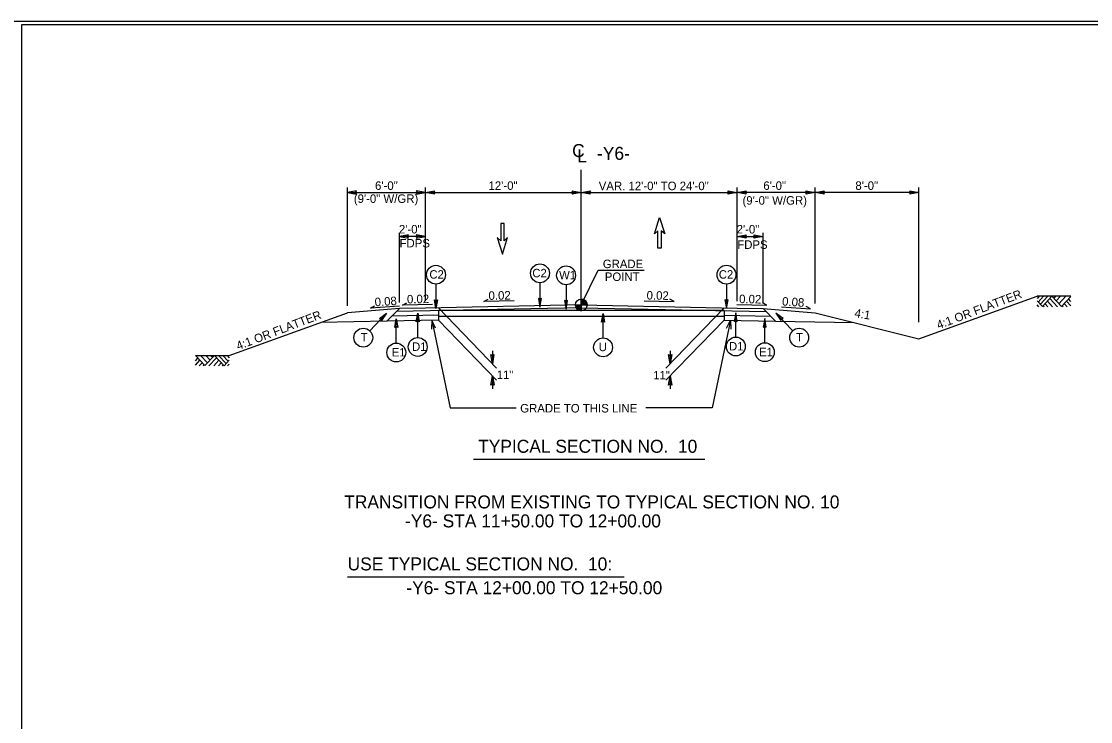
# Model space of a CAD drawing. Extents: x 1901670 to 1902225, y 193498 to 194278.
# Drawn here: x 1901982.5 to 1902064.8, y 193661.9 to 193715.8 of the extents above; entities that cross this region are included whole.
import ezdxf

# ---------------------------------------------------------------- set-up
doc = ezdxf.new("R2010")
doc.units = 0
for name, color, linetype in [('Old_Level_1', 7, 'Continuous'), ('Old_Level_11', 7, 'Continuous'), ('Old_Level_2', 7, 'Continuous'), ('Old_Level_20', 7, 'Continuous'), ('Prop Dimension', 7, 'Continuous'), ('Prop Dimension Text', 7, 'Continuous'), ('Sheet Border Standard 30in CELL', 7, 'Continuous'), ('Sheet Plot Border Inside CELL', 7, 'Continuous'), ('Typical Hinge Slope Interstate CELL', 7, 'Continuous'), ('Typical Pavement Slope CELL', 7, 'Continuous'), ('Typical Terminator CELL', 7, 'Continuous'), ('Typical Text Grade Point CELL', 7, 'Continuous')]:
    doc.layers.add(name, color=color, linetype=linetype)

# ---------------------------------------------------------------- blocks, each defined once
blk = doc.blocks.new('TERMINATOR')
at = {"layer": 'Typical Terminator CELL'}
blk.add_lwpolyline([(-0.469, 0.081), (0, 0), (-0.471, -0.083), (-0.411, 0)], close=True, dxfattribs=at)

msp = doc.modelspace()

# ---------------------------------------------------------------- linework, layer by layer
at = {"layer": 'Old_Level_1'}
for p, q in [((1902025.621, 193693.956), (1902025.621, 193704.336)), ((1902043.616, 193694.065), (1902043.616, 193702.976)), ((1902018.135, 193694.218), (1902018.468, 193694.385)), ((1902020.45, 193694.267), (1902018.135, 193694.218)), ((1902025.621, 193693.956), (1902025.621, 193694.406)), ((1902030.469, 193694.267), (1902032.784, 193694.218)), ((1902032.784, 193694.218), (1902032.451, 193694.385)), ((1902060.879, 193694.619), (1902060.709, 193694.436)), ((1902061.113, 193693.822), (1902060.709, 193694.257)), ((1902061.199, 193694.619), (1902060.785, 193694.175)), ((1902061.532, 193694.619), (1902060.952, 193693.996)), ((1902061.854, 193694.618), (1902061.113, 193693.822)), ((1902061.905, 193693.814), (1902061.505, 193694.243)), ((1902062.275, 193693.814), (1902061.689, 193694.442)), ((1902062.586, 193693.832), (1902061.854, 193694.618)), ((1902062.118, 193694.619), (1902061.985, 193694.476)), ((1902062.52, 193694.619), (1902062.187, 193694.26)), ((1902062.918, 193694.619), (1902062.385, 193694.046)), ((1902063.309, 193694.611), (1902062.586, 193693.832)), ((1902063.309, 193693.877), (1902062.967, 193694.243)), ((1902063.309, 193694.209), (1902063.124, 193694.41)), ((1902011.621, 193693.676), (1902007.621, 193693.343)), ((1902009.391, 193693.706), (1902009.716, 193693.888)), ((1902011.626, 193693.852), (1902009.391, 193693.706)), ((1902010.654, 193692.709), (1902011.621, 193693.676)), ((1902025.621, 193693.737), (1902011.398, 193693.453)), ((1902013.621, 193693.716), (1902011.621, 193693.676)), ((1902011.859, 193693.943), (1902012.192, 193694.11)), ((1902014.174, 193693.992), (1902011.859, 193693.943)), ((1902025.621, 193693.956), (1902013.621, 193693.716)), ((1902014.623, 193693.736), (1902019.098, 193689.099)), ((1902036.614, 193693.517), (1902014.623, 193693.517)), ((1902014.623, 193693.517), (1902014.623, 193692.788)), ((1902025.171, 193693.956), (1902025.621, 193693.956)), ((1902025.62, 193693.506), (1902025.621, 193693.956)), ((1902025.621, 193693.956), (1902025.62, 193693.506)), ((1902026.071, 193693.956), (1902025.621, 193693.956)), ((1902025.621, 193693.956), (1902037.616, 193693.716)), ((1902025.621, 193693.737), (1902039.84, 193693.453)), ((1902036.614, 193693.736), (1902032.14, 193689.099)), ((1902036.614, 193693.517), (1902036.614, 193692.789)), ((1902037.587, 193693.986), (1902039.903, 193693.938)), ((1902037.616, 193693.716), (1902039.616, 193693.676)), ((1902039.903, 193693.938), (1902039.57, 193694.105)), ((1902040.583, 193692.709), (1902039.616, 193693.676)), ((1902039.616, 193693.676), (1902043.616, 193693.343)), ((1902041.028, 193693.803), (1902043.263, 193693.658)), ((1902043.263, 193693.658), (1902042.938, 193693.839)), ((1902060.843, 193693.814), (1902060.709, 193693.957)), ((1902061.244, 193693.814), (1902061.175, 193693.888)), ((1902061.539, 193693.814), (1902061.322, 193694.047)), ((1902062.711, 193693.814), (1902062.639, 193693.89)), ((1902063.021, 193693.814), (1902062.794, 193694.057)), ((1902010.654, 193692.709), (1902005.581, 193692.608)), ((1902014.623, 193692.788), (1902010.654, 193692.709)), ((1902014.623, 193693.153), (1902011.026, 193693.081)), ((1902036.614, 193693.07), (1902014.623, 193693.07)), ((1902014.623, 193692.788), (1902019.1, 193688.164)), ((1902036.614, 193692.789), (1902032.138, 193688.164)), ((1902036.614, 193693.153), (1902040.211, 193693.081)), ((1902036.614, 193692.789), (1902040.583, 193692.709)), ((1902040.583, 193692.709), (1902046.635, 193692.588)), ((1902043.616, 193693.343), (1902051.616, 193691.343)), ((1902018.779, 193690.428), (1902018.779, 193689.428)), ((1902032.459, 193690.428), (1902032.459, 193689.428)), ((1901995.928, 193690.059), (1901996.652, 193689.28)), ((1901995.928, 193689.658), (1901996.114, 193689.858)), ((1901995.928, 193689.325), (1901996.27, 193689.691)), ((1901996.216, 193689.262), (1901996.443, 193689.505)), ((1901996.319, 193690.067), (1901996.852, 193689.494)), ((1901996.527, 193689.262), (1901996.598, 193689.338)), ((1901996.652, 193689.28), (1901997.383, 193690.066)), ((1901996.717, 193690.067), (1901997.05, 193689.708)), ((1901996.962, 193689.262), (1901997.548, 193689.89)), ((1901997.119, 193690.067), (1901997.252, 193689.924)), ((1901997.332, 193689.262), (1901997.732, 193689.691)), ((1901997.383, 193690.066), (1901998.124, 193689.27)), ((1901997.698, 193689.262), (1901997.915, 193689.495)), ((1901997.705, 193690.067), (1901998.285, 193689.444)), ((1901997.993, 193689.262), (1901998.062, 193689.336)), ((1901998.038, 193690.067), (1901998.452, 193689.623)), ((1901998.124, 193689.27), (1901998.528, 193689.705)), ((1901998.358, 193690.067), (1901998.528, 193689.884)), ((1901998.394, 193689.262), (1901998.528, 193689.405)), ((1902018.781, 193688.493), (1902018.781, 193687.493)), ((1902032.457, 193688.493), (1902032.457, 193687.493))]:
    msp.add_line(p, q, dxfattribs=at)
for points in [[(1902025.625, 193694.406), (1902025.625, 193694.406), (1902025.625, 193693.956)], [(1902025.634, 193694.406), (1902025.634, 193693.956)], [(1902025.643, 193694.405), (1902025.643, 193693.956)], [(1902025.652, 193694.405), (1902025.652, 193693.956)], [(1902025.661, 193694.404), (1902025.661, 193693.956)], [(1902025.67, 193694.403), (1902025.67, 193693.956)], [(1902025.679, 193694.402), (1902025.679, 193693.956)], [(1902025.688, 193694.401), (1902025.688, 193693.956)], [(1902025.697, 193694.4), (1902025.697, 193693.956)], [(1902025.706, 193694.398), (1902025.706, 193693.956)], [(1902025.715, 193694.396), (1902025.715, 193693.956)], [(1902025.724, 193694.394), (1902025.724, 193693.956)], [(1902025.733, 193694.392), (1902025.733, 193693.956)], [(1902025.742, 193694.389), (1902025.742, 193693.956)], [(1902025.751, 193694.387), (1902025.751, 193693.956)], [(1902025.76, 193694.384), (1902025.76, 193693.956)], [(1902025.769, 193694.381), (1902025.769, 193693.956)], [(1902025.778, 193694.378), (1902025.778, 193693.956)], [(1902025.787, 193694.374), (1902025.787, 193693.956)], [(1902025.796, 193694.37), (1902025.796, 193693.956)], [(1902025.805, 193694.366), (1902025.805, 193693.956)], [(1902025.814, 193694.362), (1902025.814, 193693.956)], [(1902025.823, 193694.358), (1902025.823, 193693.956)], [(1902025.832, 193694.353), (1902025.832, 193693.956)], [(1902025.841, 193694.348), (1902025.841, 193693.956)], [(1902025.85, 193694.343), (1902025.85, 193693.956)], [(1902025.859, 193694.338), (1902025.859, 193693.956)], [(1902025.868, 193694.332), (1902025.868, 193693.956)], [(1902025.877, 193694.326), (1902025.877, 193693.956)], [(1902025.886, 193694.319), (1902025.886, 193693.956)], [(1902025.895, 193694.313), (1902025.895, 193693.956)], [(1902025.904, 193694.306), (1902025.904, 193693.956)], [(1902025.913, 193694.298), (1902025.913, 193693.956)], [(1902025.922, 193694.29), (1902025.922, 193693.956)], [(1902025.931, 193694.282), (1902025.931, 193693.956)], [(1902025.94, 193694.273), (1902025.94, 193693.956)], [(1902025.949, 193694.264), (1902025.949, 193693.956)], [(1902025.958, 193694.254), (1902025.958, 193693.956)], [(1902025.967, 193694.243), (1902025.967, 193693.956)], [(1902025.976, 193694.232), (1902025.976, 193693.956)], [(1902063.309, 193694.619), (1902060.709, 193694.619)], [(1902025.173, 193693.956), (1902025.173, 193693.907)], [(1902025.182, 193693.956), (1902025.182, 193693.854)], [(1902025.191, 193693.956), (1902025.191, 193693.822)], [(1902025.2, 193693.956), (1902025.2, 193693.795)], [(1902025.209, 193693.956), (1902025.209, 193693.774)], [(1902025.218, 193693.956), (1902025.218, 193693.755)], [(1902025.227, 193693.956), (1902025.227, 193693.738)], [(1902025.236, 193693.956), (1902025.236, 193693.722)], [(1902025.245, 193693.956), (1902025.245, 193693.708)], [(1902025.254, 193693.956), (1902025.254, 193693.695)], [(1902025.263, 193693.956), (1902025.263, 193693.683)], [(1902025.272, 193693.956), (1902025.272, 193693.672)], [(1902025.281, 193693.956), (1902025.281, 193693.661)], [(1902025.29, 193693.956), (1902025.29, 193693.651)], [(1902025.299, 193693.956), (1902025.299, 193693.641)], [(1902025.308, 193693.956), (1902025.308, 193693.632)], [(1902025.317, 193693.956), (1902025.317, 193693.624)], [(1902025.326, 193693.956), (1902025.326, 193693.616)], [(1902025.335, 193693.956), (1902025.335, 193693.608)], [(1902025.344, 193693.956), (1902025.344, 193693.601)], [(1902025.353, 193693.956), (1902025.353, 193693.594)], [(1902025.362, 193693.956), (1902025.362, 193693.588)], [(1902025.371, 193693.956), (1902025.371, 193693.582)], [(1902025.38, 193693.956), (1902025.38, 193693.576)], [(1902025.389, 193693.956), (1902025.389, 193693.57)], [(1902025.398, 193693.956), (1902025.398, 193693.565)], [(1902025.407, 193693.956), (1902025.407, 193693.56)], [(1902025.416, 193693.956), (1902025.416, 193693.555)], [(1902025.425, 193693.956), (1902025.425, 193693.551)], [(1902025.434, 193693.956), (1902025.434, 193693.547)], [(1902025.443, 193693.956), (1902025.443, 193693.543)], [(1902025.452, 193693.956), (1902025.452, 193693.539)], [(1902025.461, 193693.956), (1902025.461, 193693.535)], [(1902025.47, 193693.956), (1902025.47, 193693.532)], [(1902025.479, 193693.956), (1902025.479, 193693.529)], [(1902025.488, 193693.956), (1902025.488, 193693.526)], [(1902025.497, 193693.956), (1902025.497, 193693.524)], [(1902025.506, 193693.956), (1902025.506, 193693.521)], [(1902025.515, 193693.956), (1902025.515, 193693.519)], [(1902025.524, 193693.956), (1902025.524, 193693.517)], [(1902025.533, 193693.956), (1902025.533, 193693.515)], [(1902025.542, 193693.956), (1902025.542, 193693.513)], [(1902025.551, 193693.956), (1902025.551, 193693.512)], [(1902025.56, 193693.956), (1902025.56, 193693.51)], [(1902025.569, 193693.956), (1902025.569, 193693.509)], [(1902025.578, 193693.956), (1902025.578, 193693.508)], [(1902025.587, 193693.956), (1902025.587, 193693.507)], [(1902025.596, 193693.956), (1902025.596, 193693.507)], [(1902025.605, 193693.956), (1902025.605, 193693.506)], [(1902025.614, 193693.956), (1902025.614, 193693.506), (1902025.614, 193693.506)], [(1902025.985, 193694.22), (1902025.985, 193693.956)], [(1902025.994, 193694.207), (1902025.994, 193693.956)], [(1902026.003, 193694.193), (1902026.003, 193693.956)], [(1902026.012, 193694.178), (1902026.012, 193693.956)], [(1902026.021, 193694.162), (1902026.021, 193693.956)], [(1902026.03, 193694.143), (1902026.03, 193693.956)], [(1902026.039, 193694.122), (1902026.039, 193693.956)], [(1902026.048, 193694.097), (1902026.048, 193693.956)], [(1902026.057, 193694.066), (1902026.057, 193693.956)], [(1902026.066, 193694.02), (1902026.066, 193693.956)], [(1902014.405, 193692.161), (1902014.112, 193692.77), (1902014.084, 193692.095)], [(1902014.112, 193692.77), (1902015.519, 193686.042), (1902020.607, 193686.042)], [(1902037.096, 193692.77), (1902035.689, 193686.042), (1902030.602, 193686.042)], [(1902036.803, 193692.161), (1902037.096, 193692.77), (1902037.124, 193692.095)], [(1901995.928, 193690.067), (1901998.528, 193690.067)]]:
    msp.add_lwpolyline(points, dxfattribs=at)
msp.add_circle((1902025.621, 193693.956), 0.45, dxfattribs=at)
for start, end in [(359.99048, 89.99048), (179.99048, 269.99048)]:
    msp.add_arc((1902025.621, 193693.956), 0.45, start, end, dxfattribs=at)
at = {"layer": 'Old_Level_11'}
for p, q in [((1902014.44, 193695.555), (1902014.44, 193693.681)), ((1902022.445, 193695.659), (1902022.445, 193693.785)), ((1902024.453, 193695.505), (1902024.453, 193693.631)), ((1902036.798, 193695.555), (1902036.798, 193693.681)), ((1902009.346, 193691.96), (1902010.636, 193693.319)), ((1902011.384, 193691.015), (1902011.384, 193692.889)), ((1902013.033, 193691.447), (1902013.033, 193693.322)), ((1902027.299, 193691.415), (1902027.299, 193693.29)), ((1902037.515, 193691.479), (1902037.515, 193693.353)), ((1902039.747, 193691.039), (1902039.747, 193692.913)), ((1902041.897, 193691.96), (1902040.606, 193693.319)), ((1902017.328, 193682.081), (1902035.127, 193682.081)), ((1902007.638, 193673.031), (1902028.934, 193673.031))]:
    msp.add_line(p, q, dxfattribs=at)
for points in [[(1902014.555, 193694.353), (1902014.44, 193693.681), (1902014.32, 193694.356), (1902014.44, 193694.27)], [(1902022.329, 193694.456), (1902022.445, 193693.785), (1902022.564, 193694.46), (1902022.445, 193694.374)], [(1902024.338, 193694.302), (1902024.453, 193693.631), (1902024.573, 193694.306), (1902024.453, 193694.22)], [(1902036.682, 193694.353), (1902036.798, 193693.681), (1902036.917, 193694.356), (1902036.798, 193694.271)], [(1902010.09, 193692.911), (1902010.636, 193693.319), (1902010.258, 193692.747), (1902010.23, 193692.891)], [(1902011.268, 193692.218), (1902011.384, 193692.889), (1902011.503, 193692.214), (1902011.384, 193692.3)], [(1902012.917, 193692.65), (1902013.033, 193693.322), (1902013.152, 193692.646), (1902013.033, 193692.732)], [(1902027.183, 193692.618), (1902027.299, 193693.29), (1902027.418, 193692.614), (1902027.299, 193692.7)], [(1902037.63, 193692.682), (1902037.515, 193693.353), (1902037.395, 193692.678), (1902037.515, 193692.764)], [(1902039.862, 193692.242), (1902039.747, 193692.913), (1902039.627, 193692.238), (1902039.747, 193692.324)], [(1902041.152, 193692.911), (1902040.606, 193693.319), (1902040.984, 193692.747), (1902041.012, 193692.891)]]:
    msp.add_lwpolyline(points, close=True, dxfattribs=at)
for centre in [(1902014.44, 193696.28), (1902022.445, 193696.384), (1902024.453, 193696.23), (1902036.798, 193696.281), (1902008.846, 193691.434), (1902042.396, 193691.434), (1902011.384, 193690.29), (1902013.033, 193690.722), (1902027.299, 193690.69), (1902037.515, 193690.754), (1902039.747, 193690.314)]:
    msp.add_circle(centre, 0.725, dxfattribs=at)
at = {"layer": 'Prop Dimension'}
for p, q in [((1902013.621, 193695.285), (1902013.621, 193702.976)), ((1902013.621, 193702.606), (1902025.621, 193702.606)), ((1902025.616, 193702.606), (1902037.616, 193702.606)), ((1902037.616, 193695.285), (1902037.616, 193702.976))]:
    msp.add_line(p, q, dxfattribs=at)
for points in [[(1902019.945, 193699.136), (1902019.675, 193698.886), (1902019.675, 193700.22), (1902019.425, 193700.22), (1902019.425, 193698.886), (1902019.154, 193699.136), (1902019.55, 193697.865)], [(1902019.945, 193699.136), (1902019.675, 193698.886), (1902019.675, 193700.22), (1902019.425, 193700.22), (1902019.425, 193698.886), (1902019.154, 193699.136), (1902019.55, 193697.865)], [(1902032.042, 193699.414), (1902031.771, 193699.664), (1902031.771, 193698.331), (1902031.521, 193698.331), (1902031.521, 193699.664), (1902031.25, 193699.414), (1902031.646, 193700.685)], [(1902032.042, 193699.414), (1902031.771, 193699.664), (1902031.771, 193698.331), (1902031.521, 193698.331), (1902031.521, 193699.664), (1902031.25, 193699.414), (1902031.646, 193700.685)]]:
    msp.add_lwpolyline(points, close=True, dxfattribs=at)
at = {"layer": 'Prop Dimension Text'}
for p, q in [((1902007.621, 193694.122), (1902007.621, 193702.976)), ((1902007.621, 193693.879), (1902007.621, 193702.976)), ((1902007.621, 193702.606), (1902013.621, 193702.606)), ((1902013.621, 193694.232), (1902013.621, 193702.976)), ((1902037.616, 193694.232), (1902037.616, 193702.976)), ((1902043.616, 193702.606), (1902037.616, 193702.606)), ((1902051.616, 193702.606), (1902043.616, 193702.606)), ((1902051.616, 193692.628), (1902051.616, 193702.976)), ((1902011.621, 193694.142), (1902011.621, 193699.503)), ((1902013.621, 193699.22), (1902011.621, 193699.22)), ((1902037.616, 193699.221), (1902039.616, 193699.221)), ((1902039.616, 193694.143), (1902039.616, 193699.503))]:
    msp.add_line(p, q, dxfattribs=at)
at = {"layer": 'Sheet Border Standard 30in CELL'}
msp.add_line((1901982.644, 193715.514), (1901982.644, 193715.514), dxfattribs=at)
msp.add_lwpolyline([(1902132.544, 193715.514), (1901982.544, 193715.514), (1901982.544, 193610.514), (1902132.544, 193610.514)], close=True, dxfattribs=at)
at = {"layer": 'Sheet Plot Border Inside CELL'}
msp.add_lwpolyline([(1902133.794, 193715.769), (1901967.144, 193715.769), (1901967.144, 193610.259), (1902133.794, 193610.259)], close=True, dxfattribs=at)
at = {"layer": 'Typical Pavement Slope CELL'}
for p, q in [((1902051.616, 193691.343), (1902060.709, 193694.619)), ((1901998.528, 193690.067), (1902007.621, 193693.343))]:
    msp.add_line(p, q, dxfattribs=at)
at = {"layer": 'Typical Text Grade Point CELL'}
for p, q in [((1902025.621, 193693.956), (1902026.917, 193696.629)), ((1902026.917, 193696.629), (1902030.455, 193696.629))]:
    msp.add_line(p, q, dxfattribs=at)

# ---------------------------------------------------------------- block references
at = {"layer": 'Old_Level_1', "xscale": 1.5, "yscale": 1.5}
for p, rotation in [((1902018.779, 193689.428), -90), ((1902032.459, 193689.428), -90), ((1902018.781, 193688.493), 90), ((1902032.457, 193688.493), 90)]:
    msp.add_blockref('TERMINATOR', p, dxfattribs=dict(at, rotation=rotation))
at = {"layer": 'Prop Dimension', "xscale": 1.5, "rotation": 180}
for p, yscale in [((1902007.621, 193702.606), -1.5), ((1902013.621, 193702.606), 1.5), ((1902025.616, 193702.606), 1.5), ((1902037.616, 193702.606), 1.5), ((1902043.616, 193702.606), 1.5), ((1902011.621, 193699.22), -1.5), ((1902037.616, 193699.221), 1.5)]:
    msp.add_blockref('TERMINATOR', p, dxfattribs=dict(at, yscale=yscale))
at = {"layer": 'Prop Dimension', "xscale": 1.5}
for p, yscale in [((1902013.621, 193702.606), -1.5), ((1902025.621, 193702.606), 1.5), ((1902037.616, 193702.606), 1.5), ((1902043.616, 193702.606), 1.5), ((1902051.616, 193702.606), 1.5), ((1902013.621, 193699.22), -1.5), ((1902039.616, 193699.221), 1.5)]:
    msp.add_blockref('TERMINATOR', p, dxfattribs=dict(at, yscale=yscale))

# ---------------------------------------------------------------- texts
at = {"layer": 'Old_Level_1'}
for p in [(1902053.126, 193692.074), (1901999.215, 193690.47)]:
    msp.add_text('4:1 OR FLATTER', height=0.656, rotation=20.83423, dxfattribs=at).set_placement(p)
for s, height, p in [('11"', 0.6491, (1902019.118, 193688.253)), ('11"', 0.6491, (1902031.168, 193688.228)), ('GRADE TO THIS LINE', 0.656, (1902020.919, 193685.676))]:
    msp.add_text(s, height=height, dxfattribs=at).set_placement(p)
at = {"layer": 'Old_Level_11'}
for s, p in [('TYPICAL SECTION NO.  10', (1902017.684, 193682.575)), ('TRANSITION FROM EXISTING TO TYPICAL SECTION NO. 10', (1902007.378, 193678.296)), ('-Y6- STA 11+50.00 TO 12+00.00', (1902012.054, 193676.835)), ('USE TYPICAL SECTION NO.  10:', (1902007.638, 193673.525)), (' -Y6- STA 12+00.00 TO 12+50.00', (1902011.784, 193671.693))]:
    msp.add_text(s, height=1, dxfattribs=at).set_placement(p)
at = {"layer": 'Old_Level_2'}
msp.add_text('C', height=1, dxfattribs=at).set_placement((1902024.919, 193705.33))
for s, height, rotation, p in [('L', 1, 359.9469, (1902025.321, 193704.926)), ('-Y6-', 1, 359.9469, (1902026.836, 193705.117)), ('0.08', 0.656, 3.71657, (1902009.74, 193693.841)), ('0.02', 0.656, 1.19158, (1902012.214, 193694.062)), ('0.02', 0.656, 1.19158, (1902018.49, 193694.337)), ('0.02', 0.656, 358.80842, (1902030.646, 193694.374)), ('0.02', 0.656, 358.80842, (1902037.764, 193694.094)), ('0.08', 0.656, 356.28343, (1902041.064, 193693.912))]:
    msp.add_text(s, height=height, rotation=rotation, dxfattribs=at).set_placement(p)
at = {"layer": 'Old_Level_20'}
for s, height, p in [('C2', 0.6491, (1902021.856, 193696.078)), ('C2', 0.6491, (1902013.934, 193695.974)), ('W1', 0.6491, (1902023.916, 193695.924)), ('C2', 0.6491, (1902036.209, 193695.974)), ('T', 0.649, (1902008.644, 193691.142)), ('T', 0.649, (1902042.159, 193691.142)), ('D1', 0.6491, (1902012.6, 193690.419)), ('U', 0.649, (1902026.971, 193690.397)), ('D1', 0.6491, (1902036.993, 193690.45)), ('E1', 0.6491, (1902011.039, 193689.986)), ('E1', 0.6491, (1902039.313, 193690.01))]:
    msp.add_text(s, height=height, dxfattribs=at).set_placement(p)
at = {"layer": 'Prop Dimension'}
for s, p in [('12\'-0" ', (1902018.484, 193702.804)), ('VAR. 12\'-0" TO 24\'-0" ', (1902026.965, 193702.783)), ('8\'-0" ', (1902046.72, 193702.804))]:
    msp.add_text(s, height=0.656, dxfattribs=at).set_placement(p)
at = {"layer": 'Prop Dimension Text'}
for s, p in [('6\'-0"', (1902009.748, 193702.804)), ('6\'-0"', (1902039.635, 193702.804)), ('(9\'-0" W/GR)', (1902008.115, 193701.803)), ('(9\'-0" W/GR)', (1902038.032, 193701.665)), ('2\'-0"', (1902011.586, 193699.45)), ('FDPS', (1902011.633, 193698.375)), ('FDPS', (1902037.628, 193698.264))]:
    msp.add_text(s, height=0.656, dxfattribs=at).set_placement(p)
msp.add_text('2\'-0"', height=0.656, rotation=360, dxfattribs=at).set_placement((1902037.581, 193699.45))
at = {"layer": 'Typical Hinge Slope Interstate CELL'}
msp.add_text('4:1', height=0.656, rotation=350.53768, dxfattribs=at).set_placement((1902046.619, 193693.021))
at = {"layer": 'Typical Text Grade Point CELL'}
for s, p in [('GRADE', (1902027.281, 193696.785)), ('POINT', (1902027.438, 193695.797))]:
    msp.add_text(s, height=0.6525, dxfattribs=at).set_placement(p)

doc.saveas('drawing.dxf')
